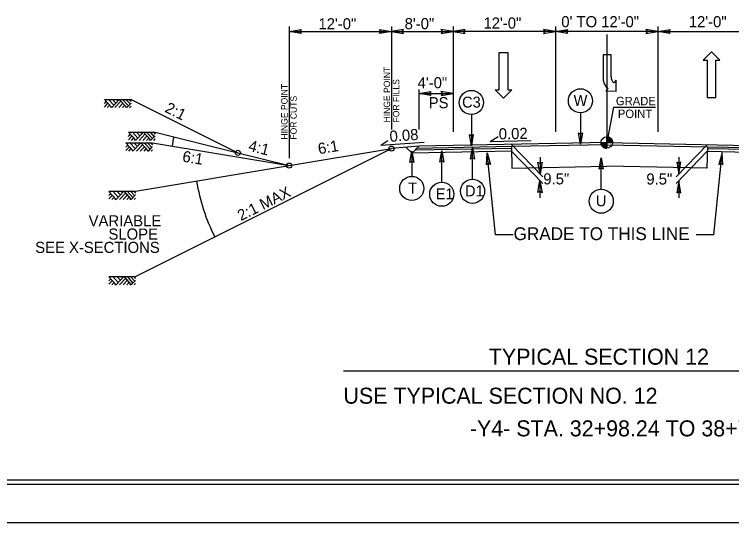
# Model space of a CAD drawing. Extents: x 1904401 to 1905163, y 193929 to 194736.
# Drawn here: x 1904832.2 to 1904916.2, y 194254.3 to 194313.9 of the extents above; entities that cross this region are included whole.
import ezdxf

# ---------------------------------------------------------------- set-up
doc = ezdxf.new("R2010")
doc.units = 0
for name, color, linetype in [('Old_Level_1', 7, 'Continuous'), ('Old_Level_11', 7, 'Continuous'), ('Old_Level_20', 7, 'Continuous'), ('Old_Level_3', 7, 'Continuous'), ('Prop Dimension Text', 7, 'Continuous'), ('Prop Lane Arrow CELL', 7, 'Continuous'), ('Sheet Cutting Line CELL', 7, 'Continuous'), ('Sheet Plot Border Inside CELL', 7, 'Continuous'), ('Sheet Plot Border Outside CELL', 7, 'Continuous'), ('Sheet Typical CELL', 7, 'Continuous'), ('Typical Arrow Superelevation CELL', 7, 'Continuous'), ('Typical Berm CELL', 7, 'Continuous'), ('Typical Hinge Slope Arterial CELL', 7, 'Continuous'), ('Typical Terminator CELL', 7, 'Continuous'), ('Typical Text Centerline CELL', 7, 'Continuous')]:
    doc.layers.add(name, color=color, linetype=linetype)

# ---------------------------------------------------------------- blocks, each defined once
blk = doc.blocks.new('TERMINATOR')
at = {"layer": 'Typical Terminator CELL'}
blk.add_lwpolyline([(-0.469, 0.081), (0, 0), (-0.471, -0.083), (-0.411, 0)], close=True, dxfattribs=at)

msp = doc.modelspace()

# ---------------------------------------------------------------- linework, layer by layer
at = {"layer": 'Old_Level_1'}
for p, q in [((1904900.918, 194298.857), (1904901.593, 194298.857)), ((1904901.592, 194298.182), (1904901.593, 194298.857)), ((1904901.593, 194298.857), (1904901.592, 194298.182)), ((1904901.593, 194298.857), (1904901.593, 194299.532)), ((1904902.268, 194298.857), (1904901.593, 194298.857)), ((1904890.418, 194298.634), (1904894.092, 194294.838)), ((1904913.387, 194298.621), (1904909.712, 194294.826)), ((1904890.434, 194297.842), (1904894.09, 194294.065)), ((1904893.776, 194297.164), (1904893.776, 194295.164)), ((1904913.371, 194297.83), (1904909.715, 194294.053)), ((1904910.028, 194297.152), (1904910.028, 194295.152)), ((1904893.769, 194294.397), (1904893.769, 194292.397)), ((1904910.036, 194294.385), (1904910.036, 194292.385))]:
    msp.add_line(p, q, dxfattribs=at)
for points in [[(1904900.921, 194298.857), (1904900.921, 194298.784)], [(1904900.935, 194298.857), (1904900.935, 194298.704)], [(1904900.948, 194298.857), (1904900.948, 194298.656)], [(1904900.962, 194298.857), (1904900.962, 194298.616)], [(1904900.975, 194298.857), (1904900.975, 194298.584)], [(1904900.989, 194298.857), (1904900.989, 194298.556)], [(1904901.002, 194298.857), (1904901.002, 194298.53)], [(1904901.016, 194298.857), (1904901.016, 194298.506)], [(1904901.029, 194298.857), (1904901.029, 194298.485)], [(1904901.043, 194298.857), (1904901.043, 194298.466)], [(1904901.056, 194298.857), (1904901.056, 194298.448)], [(1904901.07, 194298.857), (1904901.07, 194298.431)], [(1904901.083, 194298.857), (1904901.083, 194298.415)], [(1904901.097, 194298.857), (1904901.097, 194298.4)], [(1904901.11, 194298.857), (1904901.11, 194298.385)], [(1904901.124, 194298.857), (1904901.124, 194298.371)], [(1904901.137, 194298.857), (1904901.137, 194298.359)], [(1904901.151, 194298.857), (1904901.151, 194298.347)], [(1904901.164, 194298.857), (1904901.164, 194298.335)], [(1904901.178, 194298.857), (1904901.178, 194298.325)], [(1904901.191, 194298.857), (1904901.191, 194298.314)], [(1904901.205, 194298.857), (1904901.205, 194298.305)], [(1904901.218, 194298.857), (1904901.218, 194298.296)], [(1904901.232, 194298.857), (1904901.232, 194298.287)], [(1904901.245, 194298.857), (1904901.245, 194298.278)], [(1904901.259, 194298.857), (1904901.259, 194298.271)], [(1904901.272, 194298.857), (1904901.272, 194298.263)], [(1904901.286, 194298.857), (1904901.286, 194298.256)], [(1904901.299, 194298.857), (1904901.299, 194298.25)], [(1904901.313, 194298.857), (1904901.313, 194298.244)], [(1904901.326, 194298.857), (1904901.326, 194298.238)], [(1904901.34, 194298.857), (1904901.34, 194298.232)], [(1904901.353, 194298.857), (1904901.353, 194298.226)], [(1904901.367, 194298.857), (1904901.367, 194298.221)], [(1904901.38, 194298.857), (1904901.38, 194298.217)], [(1904901.394, 194298.857), (1904901.394, 194298.212)], [(1904901.407, 194298.857), (1904901.407, 194298.209)], [(1904901.421, 194298.857), (1904901.421, 194298.205)], [(1904901.434, 194298.857), (1904901.434, 194298.202)], [(1904901.448, 194298.857), (1904901.448, 194298.199)], [(1904901.461, 194298.857), (1904901.461, 194298.196)], [(1904901.475, 194298.857), (1904901.475, 194298.193)], [(1904901.488, 194298.857), (1904901.488, 194298.191)], [(1904901.502, 194298.857), (1904901.502, 194298.188)], [(1904901.515, 194298.857), (1904901.515, 194298.187)], [(1904901.529, 194298.857), (1904901.529, 194298.185)], [(1904901.542, 194298.857), (1904901.542, 194298.184)], [(1904901.556, 194298.857), (1904901.556, 194298.184)], [(1904901.569, 194298.857), (1904901.569, 194298.182)], [(1904901.583, 194298.857), (1904901.583, 194298.182), (1904901.583, 194298.182)], [(1904901.599, 194299.532), (1904901.599, 194299.532), (1904901.599, 194298.857)], [(1904901.613, 194299.532), (1904901.613, 194298.857)], [(1904901.626, 194299.531), (1904901.626, 194298.857)], [(1904901.64, 194299.531), (1904901.64, 194298.857)], [(1904901.653, 194299.529), (1904901.653, 194298.857)], [(1904901.667, 194299.528), (1904901.667, 194298.857)], [(1904901.68, 194299.526), (1904901.68, 194298.857)], [(1904901.694, 194299.525), (1904901.694, 194298.857)], [(1904901.707, 194299.523), (1904901.707, 194298.857)], [(1904901.721, 194299.52), (1904901.721, 194298.857)], [(1904901.734, 194299.517), (1904901.734, 194298.857)], [(1904901.748, 194299.514), (1904901.748, 194298.857)], [(1904901.761, 194299.511), (1904901.761, 194298.857)], [(1904901.775, 194299.507), (1904901.775, 194298.857)], [(1904901.788, 194299.504), (1904901.788, 194298.857)], [(1904901.802, 194299.499), (1904901.802, 194298.857)], [(1904901.815, 194299.495), (1904901.815, 194298.857)], [(1904901.829, 194299.49), (1904901.829, 194298.857)], [(1904901.842, 194299.484), (1904901.842, 194298.857)], [(1904901.856, 194299.478), (1904901.856, 194298.857)], [(1904901.869, 194299.472), (1904901.869, 194298.857)], [(1904901.883, 194299.466), (1904901.883, 194298.857)], [(1904901.896, 194299.46), (1904901.896, 194298.857)], [(1904901.91, 194299.453), (1904901.91, 194298.857)], [(1904901.923, 194299.445), (1904901.923, 194298.857)], [(1904901.937, 194299.438), (1904901.937, 194298.857)], [(1904901.95, 194299.43), (1904901.95, 194298.857)], [(1904901.964, 194299.421), (1904901.964, 194298.857)], [(1904901.977, 194299.412), (1904901.977, 194298.857)], [(1904901.991, 194299.402), (1904901.991, 194298.857)], [(1904902.004, 194299.393), (1904902.004, 194298.857)], [(1904902.018, 194299.382), (1904902.018, 194298.857)], [(1904902.031, 194299.37), (1904902.031, 194298.857)], [(1904902.045, 194299.358), (1904902.045, 194298.857)], [(1904902.058, 194299.346), (1904902.058, 194298.857)], [(1904902.072, 194299.333), (1904902.072, 194298.857)], [(1904902.085, 194299.319), (1904902.085, 194298.857)], [(1904902.099, 194299.304), (1904902.099, 194298.857)], [(1904902.112, 194299.288), (1904902.112, 194298.857)], [(1904902.126, 194299.271), (1904902.126, 194298.857)], [(1904902.139, 194299.253), (1904902.139, 194298.857)], [(1904902.153, 194299.234), (1904902.153, 194298.857)], [(1904902.166, 194299.213), (1904902.166, 194298.857)], [(1904902.18, 194299.19), (1904902.18, 194298.857)], [(1904902.193, 194299.166), (1904902.193, 194298.857)], [(1904902.207, 194299.138), (1904902.207, 194298.857)], [(1904902.22, 194299.106), (1904902.22, 194298.857)], [(1904902.234, 194299.069), (1904902.234, 194298.857)], [(1904902.247, 194299.022), (1904902.247, 194298.857)], [(1904902.261, 194298.953), (1904902.261, 194298.857)]]:
    msp.add_lwpolyline(points, dxfattribs=at)
msp.add_circle((1904901.593, 194298.857), 0.675, dxfattribs=at)
for start, end in [(179.99048, 269.99048), (359.99048, 89.99048)]:
    msp.add_arc((1904901.593, 194298.857), 0.675, start, end, dxfattribs=at)
at = {"layer": 'Old_Level_11'}
for p, q in [((1904898.511, 194302.334), (1904898.511, 194298.679)), ((1904885.736, 194302.137), (1904885.736, 194298.483)), ((1904885.871, 194294.565), (1904885.871, 194298.22)), ((1904878.759, 194297.835), (1904878.759, 194294.901)), ((1904882.269, 194294.217), (1904882.269, 194297.871)), ((1904900.946, 194293.404), (1904900.946, 194297.058))]:
    msp.add_line(p, q, dxfattribs=at)
for points in [[(1904885.961, 194299.792), (1904885.736, 194298.483), (1904885.503, 194299.799), (1904885.736, 194299.632)], [(1904898.736, 194299.989), (1904898.511, 194298.679), (1904898.278, 194299.996), (1904898.511, 194299.828)], [(1904885.646, 194296.91), (1904885.871, 194298.22), (1904886.104, 194296.903), (1904885.871, 194297.07)], [(1904878.534, 194296.526), (1904878.759, 194297.835), (1904878.992, 194296.519), (1904878.759, 194296.686)], [(1904882.044, 194296.562), (1904882.269, 194297.871), (1904882.502, 194296.555), (1904882.269, 194296.722)], [(1904900.721, 194295.749), (1904900.946, 194297.058), (1904901.179, 194295.742), (1904900.946, 194295.909)]]:
    msp.add_lwpolyline(points, close=True, dxfattribs=at)
for centre in [(1904885.736, 194303.551), (1904898.511, 194303.748), (1904878.759, 194293.487), (1904882.269, 194292.802), (1904885.871, 194293.151), (1904900.946, 194291.99)]:
    msp.add_circle(centre, 1.414, dxfattribs=at)
at = {"layer": 'Old_Level_3'}
for q in [(1904901.593, 194298.857), (1904907.291, 194302.99)]:
    msp.add_line((1904902.376, 194302.99), q, dxfattribs=at)
at = {"layer": 'Prop Lane Arrow CELL'}
for p, q in [((1904864.395, 194312.463), (1904864.395, 194297.027)), ((1904876.393, 194312.463), (1904876.393, 194300.392)), ((1904883.593, 194312.463), (1904883.593, 194300.129)), ((1904895.593, 194312.463), (1904895.593, 194300.129)), ((1904907.593, 194312.463), (1904907.593, 194300.129)), ((1904864.395, 194311.863), (1904883.593, 194311.863)), ((1904895.593, 194311.863), (1904883.593, 194311.863)), ((1904907.593, 194311.863), (1904895.593, 194311.863)), ((1904907.593, 194311.863), (1904919.593, 194311.863)), ((1904888.987, 194309.397), (1904890.015, 194309.397)), ((1904888.987, 194305.04), (1904888.987, 194309.397)), ((1904890.015, 194309.397), (1904890.015, 194305.04)), ((1904901.173, 194309.123), (1904901.173, 194306.169)), ((1904902.097, 194309.123), (1904901.173, 194309.123)), ((1904902.097, 194306.561), (1904902.097, 194309.123)), ((1904913.873, 194309.491), (1904912.877, 194308.511)), ((1904914.838, 194308.511), (1904913.873, 194309.491)), ((1904912.877, 194308.511), (1904913.344, 194308.511)), ((1904913.344, 194308.511), (1904913.344, 194304.154)), ((1904914.371, 194304.154), (1904914.371, 194308.511)), ((1904914.371, 194308.511), (1904914.838, 194308.511)), ((1904902.713, 194306.155), (1904902.419, 194305.861)), ((1904902.699, 194304.895), (1904902.713, 194306.155)), ((1904879.593, 194305.087), (1904879.593, 194300.392)), ((1904889.517, 194304.059), (1904888.521, 194305.04)), ((1904888.521, 194305.04), (1904888.987, 194305.04)), ((1904890.481, 194305.04), (1904889.517, 194304.059)), ((1904890.015, 194305.04), (1904890.481, 194305.04)), ((1904901.761, 194305.203), (1904901.467, 194304.909)), ((1904901.467, 194304.909), (1904902.699, 194304.895)), ((1904842.756, 194303.901), (1904843.625, 194302.966)), ((1904843.226, 194303.911), (1904843.865, 194303.223)), ((1904843.625, 194302.966), (1904844.502, 194303.909)), ((1904843.703, 194303.91), (1904844.103, 194303.48)), ((1904844.185, 194303.911), (1904844.345, 194303.739)), ((1904844.502, 194303.909), (1904845.392, 194302.954)), ((1904844.889, 194303.911), (1904845.585, 194303.163)), ((1904845.288, 194303.91), (1904845.785, 194303.378)), ((1904845.672, 194303.911), (1904845.876, 194303.691)), ((1904879.593, 194304.595), (1904883.593, 194304.595)), ((1904913.344, 194304.154), (1904914.371, 194304.154)), ((1904842.756, 194303.42), (1904842.979, 194303.66)), ((1904842.756, 194303.02), (1904843.167, 194303.459)), ((1904843.102, 194302.945), (1904843.374, 194303.236)), ((1904843.475, 194302.945), (1904843.56, 194303.036)), ((1904843.997, 194302.945), (1904844.7, 194303.698)), ((1904844.441, 194302.945), (1904844.921, 194303.459)), ((1904844.88, 194302.945), (1904845.141, 194303.224)), ((1904845.392, 194302.954), (1904845.876, 194303.476)), ((1904845.716, 194302.945), (1904845.876, 194303.116)), ((1904845.234, 194302.945), (1904845.317, 194303.033)), ((1904845.576, 194300.066), (1904846.445, 194299.131)), ((1904845.576, 194299.585), (1904845.8, 194299.825)), ((1904846.046, 194300.076), (1904846.685, 194299.388)), ((1904846.445, 194299.131), (1904847.322, 194300.074)), ((1904846.523, 194300.075), (1904846.923, 194299.645)), ((1904846.817, 194299.11), (1904847.521, 194299.863)), ((1904847.006, 194300.076), (1904847.165, 194299.904)), ((1904847.322, 194300.074), (1904848.212, 194299.119)), ((1904847.709, 194300.076), (1904848.405, 194299.328)), ((1904848.108, 194300.075), (1904848.605, 194299.543)), ((1904848.493, 194300.076), (1904848.697, 194299.856)), ((1904845.576, 194299.185), (1904845.987, 194299.624)), ((1904845.922, 194299.11), (1904846.194, 194299.401)), ((1904846.295, 194299.11), (1904846.381, 194299.201)), ((1904847.261, 194299.11), (1904847.741, 194299.624)), ((1904847.7, 194299.11), (1904847.961, 194299.389)), ((1904848.054, 194299.11), (1904848.137, 194299.198)), ((1904848.212, 194299.119), (1904848.696, 194299.641)), ((1904848.536, 194299.11), (1904848.697, 194299.281)), ((1904901.593, 194298.857), (1904879.593, 194298.417)), ((1904901.593, 194298.857), (1904935.593, 194298.177)), ((1904845.278, 194298.808), (1904846.147, 194297.873)), ((1904845.278, 194298.326), (1904845.501, 194298.566)), ((1904845.278, 194297.927), (1904845.688, 194298.366)), ((1904845.624, 194297.851), (1904845.896, 194298.143)), ((1904845.747, 194298.817), (1904846.387, 194298.13)), ((1904846.147, 194297.873), (1904847.024, 194298.816)), ((1904846.225, 194298.817), (1904846.624, 194298.387)), ((1904846.519, 194297.852), (1904847.222, 194298.605)), ((1904846.707, 194298.817), (1904846.867, 194298.646)), ((1904846.963, 194297.852), (1904847.443, 194298.366)), ((1904847.024, 194298.816), (1904847.913, 194297.861)), ((1904847.402, 194297.852), (1904847.662, 194298.131)), ((1904847.41, 194298.818), (1904848.106, 194298.07)), ((1904847.81, 194298.817), (1904848.307, 194298.285)), ((1904847.913, 194297.861), (1904848.398, 194298.383)), ((1904848.194, 194298.817), (1904848.398, 194298.598)), ((1904848.237, 194297.851), (1904848.398, 194298.023)), ((1904879.593, 194298.417), (1904876.393, 194298.151)), ((1904878.785, 194297.609), (1904878.102, 194298.293)), ((1904878.785, 194297.609), (1904879.593, 194298.417)), ((1904890.427, 194298.175), (1904879.126, 194297.949)), ((1904890.423, 194298.384), (1904879.338, 194298.162)), ((1904913.377, 194298.163), (1904936.061, 194297.709)), ((1904913.382, 194298.371), (1904935.849, 194297.922)), ((1904845.997, 194297.851), (1904846.082, 194297.943)), ((1904847.756, 194297.851), (1904847.839, 194297.94)), ((1904890.434, 194297.842), (1904878.785, 194297.609)), ((1904888.566, 194288.037), (1904887.592, 194297.66)), ((1904913.371, 194297.83), (1904936.401, 194297.369)), ((1904914.144, 194288.037), (1904915.118, 194297.67)), ((1904843.278, 194293.142), (1904844.147, 194292.207)), ((1904843.748, 194293.151), (1904844.387, 194292.464)), ((1904844.147, 194292.207), (1904845.024, 194293.15)), ((1904844.225, 194293.151), (1904844.625, 194292.72)), ((1904844.707, 194293.151), (1904844.867, 194292.98)), ((1904845.024, 194293.15), (1904845.913, 194292.195)), ((1904845.411, 194293.151), (1904846.107, 194292.404)), ((1904845.81, 194293.151), (1904846.307, 194292.618)), ((1904846.194, 194293.151), (1904846.398, 194292.932)), ((1904843.278, 194292.66), (1904843.501, 194292.9)), ((1904843.278, 194292.261), (1904843.689, 194292.7)), ((1904843.624, 194292.185), (1904843.896, 194292.477)), ((1904843.997, 194292.185), (1904844.082, 194292.276)), ((1904844.519, 194292.185), (1904845.222, 194292.939)), ((1904844.963, 194292.185), (1904845.443, 194292.7)), ((1904845.402, 194292.185), (1904845.663, 194292.465)), ((1904845.756, 194292.185), (1904845.839, 194292.274)), ((1904845.913, 194292.195), (1904846.398, 194292.717)), ((1904846.237, 194292.185), (1904846.398, 194292.357)), ((1904890.645, 194288.037), (1904888.566, 194288.037)), ((1904914.144, 194288.037), (1904912.065, 194288.037)), ((1904843.278, 194283.143), (1904844.147, 194282.208)), ((1904843.278, 194282.662), (1904843.501, 194282.902)), ((1904843.748, 194283.153), (1904844.387, 194282.465)), ((1904844.147, 194282.208), (1904845.024, 194283.152)), ((1904844.225, 194283.153), (1904844.625, 194282.722)), ((1904844.519, 194282.187), (1904845.222, 194282.941)), ((1904844.707, 194283.153), (1904844.867, 194282.981)), ((1904845.024, 194283.152), (1904845.913, 194282.197)), ((1904845.411, 194283.153), (1904846.107, 194282.405)), ((1904845.81, 194283.153), (1904846.307, 194282.62)), ((1904846.194, 194283.153), (1904846.398, 194282.933)), ((1904843.278, 194282.263), (1904843.689, 194282.702)), ((1904843.624, 194282.187), (1904843.896, 194282.479)), ((1904843.997, 194282.187), (1904844.082, 194282.278)), ((1904844.963, 194282.187), (1904845.443, 194282.702)), ((1904845.402, 194282.187), (1904845.663, 194282.467)), ((1904845.756, 194282.187), (1904845.839, 194282.276)), ((1904845.913, 194282.197), (1904846.398, 194282.719)), ((1904846.237, 194282.187), (1904846.398, 194282.359)), ((1904870.763, 194272.112), (1904931.722, 194272.112))]:
    msp.add_line(p, q, dxfattribs=at)
for points in [[(1904842.756, 194303.911), (1904845.876, 194303.911)], [(1904845.576, 194300.076), (1904848.696, 194300.076)], [(1904845.278, 194298.817), (1904848.398, 194298.817)], [(1904843.278, 194293.151), (1904846.398, 194293.151)], [(1904843.278, 194283.153), (1904846.398, 194283.153)]]:
    msp.add_lwpolyline(points, dxfattribs=at)
for centre, radius, start, end in [((1904903.009, 194306.559), 0.917, 180, 229.65817), ((1904902.622, 194306.391), 1.471, 188.67607, 233.98777)]:
    msp.add_arc(centre, radius, start, end, dxfattribs=at)
at = {"layer": 'Sheet Cutting Line CELL'}
msp.add_line((1904710.692, 194254.335), (1905047.492, 194254.335), dxfattribs=at)
at = {"layer": 'Sheet Plot Border Inside CELL'}
msp.add_lwpolyline([(1905046.592, 194469.845), (1904713.292, 194469.845), (1904713.292, 194258.825), (1905046.592, 194258.825)], close=True, dxfattribs=at)
at = {"layer": 'Sheet Plot Border Outside CELL'}
msp.add_lwpolyline([(1905047.492, 194474.335), (1904710.692, 194474.335), (1904710.692, 194254.335), (1905047.492, 194254.335)], close=True, dxfattribs=at)
at = {"layer": 'Sheet Typical CELL'}
msp.add_lwpolyline([(1905044.092, 194469.335), (1904744.092, 194469.335), (1904744.092, 194259.335), (1905044.092, 194259.335)], close=True, dxfattribs=at)
at = {"layer": 'Typical Arrow Superelevation CELL'}
for p, q in [((1904875.136, 194298.54), (1904875.963, 194299.102)), ((1904875.136, 194298.54), (1904880.217, 194298.913)), ((1904887.943, 194298.993), (1904888.883, 194299.561)), ((1904887.943, 194298.993), (1904892.754, 194299.089))]:
    msp.add_line(p, q, dxfattribs=at)
at = {"layer": 'Typical Berm CELL'}
for p, q in [((1904901.607, 194298.607), (1904890.423, 194298.384)), ((1904890.423, 194298.384), (1904890.473, 194295.867)), ((1904901.596, 194298.607), (1904913.382, 194298.371)), ((1904913.382, 194298.371), (1904913.331, 194295.855)), ((1904890.473, 194295.867), (1904901.593, 194296.089)), ((1904913.331, 194295.855), (1904901.593, 194296.089))]:
    msp.add_line(p, q, dxfattribs=at)
at = {"layer": 'Typical Hinge Slope Arterial CELL'}
for p, q in [((1904845.876, 194303.911), (1904858.396, 194297.651)), ((1904848.696, 194300.076), (1904858.396, 194297.651)), ((1904846.398, 194283.153), (1904876.393, 194298.151)), ((1904848.398, 194298.817), (1904864.395, 194296.151)), ((1904864.395, 194296.151), (1904876.393, 194298.151)), ((1904858.396, 194297.651), (1904864.395, 194296.151)), ((1904846.398, 194293.151), (1904864.395, 194296.151))]:
    msp.add_line(p, q, dxfattribs=at)
for centre in [(1904876.393, 194298.151), (1904858.396, 194297.651), (1904864.395, 194296.151)]:
    msp.add_circle(centre, 0.297, dxfattribs=at)
for centre, radius, start, end in [((1904858.396, 194297.651), 7.737, 165.96369, 174.18972), ((1904876.393, 194298.151), 23.155, 189.46245, 206.56505)]:
    msp.add_arc(centre, radius, start, end, dxfattribs=at)
at = {"layer": 'Typical Terminator CELL'}
for points in [[(1904865.801, 194311.621), (1904864.395, 194311.863), (1904865.809, 194312.113), (1904865.63, 194311.863)], [(1904874.987, 194312.105), (1904876.393, 194311.863), (1904874.98, 194311.613), (1904875.159, 194311.863)], [(1904877.799, 194312.105), (1904876.393, 194311.863), (1904877.807, 194311.613), (1904877.628, 194311.863)], [(1904882.187, 194311.621), (1904883.593, 194311.863), (1904882.18, 194312.113), (1904882.359, 194311.863)], [(1904884.999, 194312.105), (1904883.593, 194311.863), (1904885.007, 194311.613), (1904884.828, 194311.863)], [(1904894.187, 194311.621), (1904895.593, 194311.863), (1904894.18, 194312.113), (1904894.359, 194311.863)], [(1904896.999, 194311.621), (1904895.593, 194311.863), (1904897.007, 194312.113), (1904896.828, 194311.863)], [(1904906.187, 194311.621), (1904907.593, 194311.863), (1904906.18, 194312.113), (1904906.359, 194311.863)], [(1904908.999, 194311.621), (1904907.593, 194311.863), (1904909.007, 194312.113), (1904908.828, 194311.863)], [(1904880.999, 194304.353), (1904879.593, 194304.595), (1904881.007, 194304.845), (1904880.828, 194304.595)], [(1904882.187, 194304.353), (1904883.593, 194304.595), (1904882.18, 194304.845), (1904882.359, 194304.595)], [(1904887.505, 194296.236), (1904887.592, 194297.66), (1904887.995, 194296.282), (1904887.727, 194296.434)], [(1904915.205, 194296.246), (1904915.118, 194297.67), (1904914.715, 194296.292), (1904914.983, 194296.443)]]:
    msp.add_lwpolyline(points, close=True, dxfattribs=at)
at = {"layer": 'Typical Text Centerline CELL'}
msp.add_line((1904901.593, 194311.504), (1904901.593, 194298.857), dxfattribs=at)

# ---------------------------------------------------------------- block references
at = {"layer": 'Old_Level_1', "xscale": 3}
for p, yscale, rotation in [((1904893.776, 194295.164), 3, -90), ((1904910.028, 194295.152), -3, -89.99999999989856), ((1904893.769, 194294.397), 3, 90), ((1904910.036, 194294.385), -3, 90.00000000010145)]:
    msp.add_blockref('TERMINATOR', p, dxfattribs=dict(at, yscale=yscale, rotation=rotation))

# ---------------------------------------------------------------- texts
at = {"layer": 'Old_Level_11'}
for s, p in [('GRADE', (1904902.66, 194303.227)), ('POINT', (1904902.897, 194301.736))]:
    msp.add_text(s, height=0.984, dxfattribs=at).set_placement(p)
at = {"layer": 'Old_Level_20'}
for s, height, p in [('C3', 1.2792, (1904884.648, 194302.954)), ('W', 1.279, (1904897.716, 194303.151)), ('9.5"', 1.3, (1904894.162, 194293.954)), ('9.5"', 1.3, (1904906.232, 194293.941)), ('T', 1.279, (1904878.323, 194292.889)), ('D1', 1.2792, (1904884.99, 194292.554)), ('E1', 1.2792, (1904881.561, 194292.205)), ('U', 1.279, (1904900.314, 194291.393))]:
    msp.add_text(s, height=height, dxfattribs=at).set_placement(p)
at = {"layer": 'Prop Dimension Text'}
msp.add_text('0.02', height=1.3, rotation=1.1462, dxfattribs=at).set_placement((1904888.958, 194299.224))
at = {"layer": 'Prop Lane Arrow CELL'}
for s, height, p in [('12\'-0"', 1.3, (1904867.828, 194312.12)), ('8\'-0"', 1.3, (1904877.925, 194312.14)), ('12\'-0"', 1.3, (1904887.154, 194312.207)), ('0\' TO 12\'-0"', 1.3, (1904896.268, 194312.364)), ('12\'-0"', 1.3, (1904911.203, 194312.364)), ('4\'-0"', 1.3, (1904879.442, 194305.214)), ('PS', 1.3, (1904880.741, 194302.875)), ('TYPICAL SECTION 12', 1.875, (1904887.785, 194272.838)), ('USE TYPICAL SECTION NO. 12', 1.875, (1904870.755, 194268.268)), ('-Y4- STA. 32+98.24 TO 38+72.95', 1.875, (1904885.564, 194264.443))]:
    msp.add_text(s, height=height, dxfattribs=at).set_placement(p)
for s, height, rotation, p in [('0.08', 1.3, 4.19823, (1904876.205, 194298.932)), ('GRADE TO THIS LINE', 1.5, 0.00016, (1904890.68, 194287.43))]:
    msp.add_text(s, height=height, rotation=rotation, dxfattribs=at).set_placement(p)
at = {"layer": 'Typical Hinge Slope Arterial CELL'}
for s, height, rotation, p in [('HINGE POINT ', 0.75, 90, (1904876.222, 194301.212)), ('HINGE POINT ', 0.75, 90, (1904864.211, 194299.204)), ('FOR FILLS', 0.75, 90, (1904877.295, 194301.212)), ('FOR CUTS', 0.75, 90, (1904865.283, 194299.204)), ('2:1', 1.3, 333.43495, (1904849.745, 194302.488)), ('4:1', 1.3, 345.96376, (1904859.543, 194297.919)), ('6:1', 1.3, 9.46232, (1904867.885, 194297.476)), ('6:1', 1.3, 350.53652, (1904851.827, 194296.636)), ('2:1 MAX', 1.3, 26.56505, (1904858.75, 194289.642))]:
    msp.add_text(s, height=height, rotation=rotation, dxfattribs=at).set_placement(p)
for s, p in [('VARIABLE ', (1904840.913, 194289.044)), ('SLOPE', (1904843.236, 194287.487)), ('SEE X-SECTIONS', (1904834.653, 194285.931))]:
    msp.add_text(s, height=1.3, dxfattribs=at).set_placement(p)

doc.saveas('drawing.dxf')
